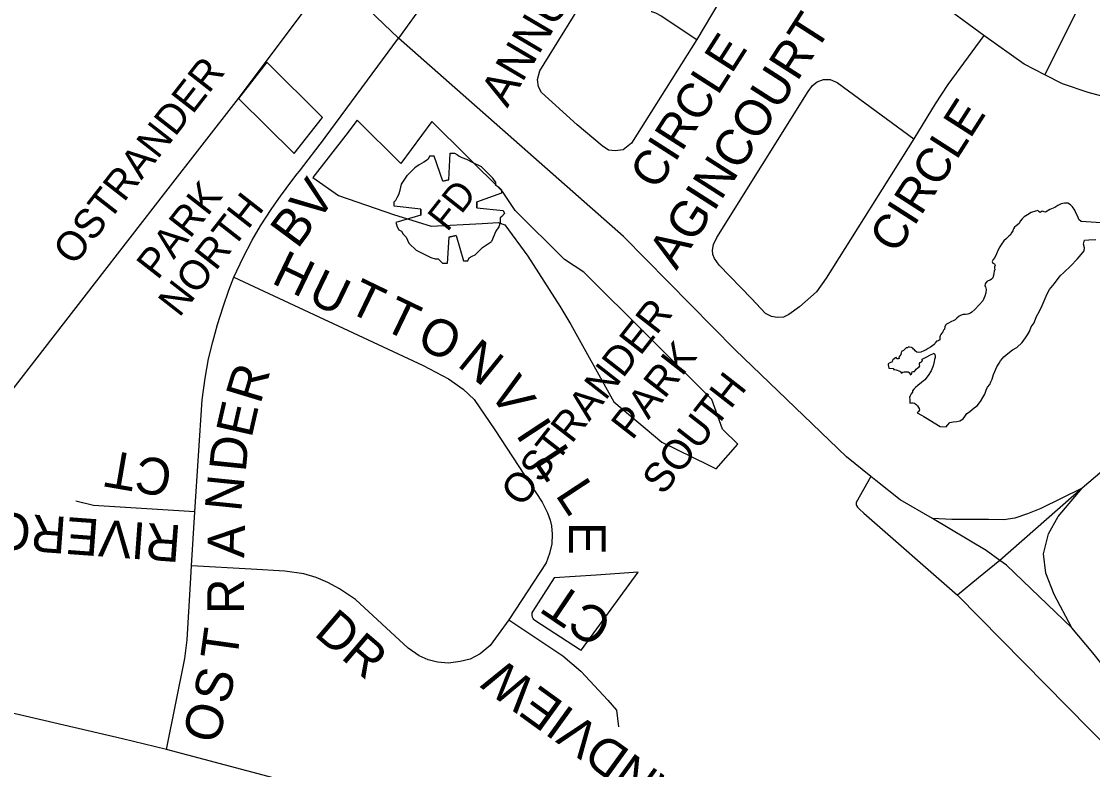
# Model space of a CAD drawing. Extents: x 586326 to 623965, y 4819854 to 4857850.
# Drawn here: x 595903 to 596631, y 4833284 to 4833792 of the extents above; entities that cross this region are included whole.
import ezdxf

# ---------------------------------------------------------------- set-up
doc = ezdxf.new("R2010")
doc.units = 0
for name, color, linetype in [('Fire Syms', 7, 'Continuous'), ('Lots_Concessions', 7, 'Continuous'), ('Major Rds and Hwys', 7, 'Continuous'), ('Minor Rd Lbls', 7, 'Continuous'), ('Minor Rds', 7, 'Continuous'), ('Park Lbls', 7, 'Continuous'), ('Park Outlines', 7, 'Continuous'), ('Proposed Secondary Rds', 7, 'Continuous'), ('SWM Ponds', 7, 'Continuous')]:
    doc.layers.add(name, color=color, linetype=linetype)

msp = doc.modelspace()

# ---------------------------------------------------------------- linework, layer by layer
at = {"layer": 'Fire Syms'}
for points in [[(596193.48, 4833684.1), (596189.48, 4833683.1), (596183.48, 4833700.1), (596180.48, 4833700.1), (596179.48, 4833698.1), (596178.48, 4833697.1), (596176.48, 4833696.1), (596173.48, 4833694.1), (596170.48, 4833692.1), (596165.48, 4833687.1), (596165.48, 4833687.1)], [(596189.48, 4833683.1), (596193.48, 4833684.1), (596194.48, 4833702.1), (596197.48, 4833702.1), (596199.48, 4833701.1), (596200.48, 4833700.1), (596202.48, 4833699.1), (596205.48, 4833698.1), (596209.48, 4833696.1), (596215.48, 4833693.1), (596215.48, 4833693.1)], [(596212.48, 4833665.1), (596212.48, 4833669.1), (596229.48, 4833675.1), (596229.48, 4833677.1), (596227.48, 4833679.1), (596225.48, 4833680.1), (596225.48, 4833682.1), (596223.48, 4833685.1), (596220.48, 4833688.1), (596215.48, 4833693.1), (596215.48, 4833693.1)], [(596174.48, 4833660.1), (596174.48, 4833664.1), (596156.48, 4833666.1), (596156.48, 4833669.1), (596157.48, 4833670.1), (596158.48, 4833672.1), (596159.48, 4833674.1), (596160.48, 4833677.1), (596161.48, 4833681.1), (596165.48, 4833687.1), (596165.48, 4833687.1)], [(596174.48, 4833664.1), (596174.48, 4833660.1), (596157.48, 4833655.1), (596158.48, 4833652.1), (596159.48, 4833650.1), (596161.48, 4833649.1), (596162.48, 4833647.1), (596164.48, 4833645.1), (596166.48, 4833641.1), (596171.48, 4833636.1), (596171.48, 4833636.1)], [(596212.48, 4833669.1), (596212.48, 4833665.1), (596230.48, 4833663.1), (596231.48, 4833661.1), (596229.48, 4833659.1), (596228.48, 4833658.1), (596228.48, 4833655.1), (596227.48, 4833652.1), (596225.48, 4833649.1), (596222.48, 4833642.1), (596222.48, 4833642.1)], [(596198.48, 4833646.1), (596193.48, 4833645.1), (596192.48, 4833627.1), (596189.48, 4833627.1), (596188.48, 4833628.1), (596186.48, 4833630.1), (596184.48, 4833630.1), (596181.48, 4833631.1), (596177.48, 4833633.1), (596171.48, 4833636.1), (596171.48, 4833636.1)], [(596193.48, 4833645.1), (596198.48, 4833646.1), (596203.48, 4833629.1), (596206.48, 4833629.1), (596207.48, 4833631.1), (596209.48, 4833632.1), (596211.48, 4833633.1), (596213.48, 4833635.1), (596216.48, 4833638.1), (596222.48, 4833642.1), (596222.48, 4833642.1)]]:
    msp.add_lwpolyline(points, dxfattribs=at)
at = {"layer": 'Lots_Concessions'}
for p, q in [((596050.57, 4833739.36), (596114.2, 4833824.24)), ((596001.39, 4833675.97), (596050.57, 4833739.36)), ((595952.86, 4833613.41), (596001.39, 4833675.97)), ((595919.29, 4833570.15), (595952.86, 4833613.41)), ((595893.72, 4833537.19), (595919.29, 4833570.15))]:
    msp.add_line(p, q, dxfattribs=at)
at = {"layer": 'Major Rds and Hwys'}
for points in [[(596159.27, 4833780.16), (596119.07, 4833818.86), (596049.17, 4833888.45), (595811.11, 4834124.39)], [(596480.17, 4833482.64), (596463.84, 4833495.81), (596388.01, 4833568.46), (596312.19, 4833645.58), (596159.27, 4833780.16)], [(596783.26, 4833664.39), (596738.71, 4833600.37), (596702.29, 4833551.85), (596673.29, 4833517.9), (596644.91, 4833492.39), (596623.81, 4833474.72)], [(596522.08, 4833454.03), (596500.2, 4833466.72), (596483.64, 4833479.84), (596480.17, 4833482.64)], [(596623.81, 4833474.72), (596595.82, 4833460.85), (596586.66, 4833457.08), (596578.01, 4833454.28), (596570.56, 4833453.15), (596560.23, 4833453.28), (596548.52, 4833453.23), (596535.26, 4833453.42), (596522.08, 4833454.03)], [(596623.81, 4833474.72), (596567.95, 4833425.57)], [(596616.94, 4833379.67), (596604.94, 4833402.45), (596599.27, 4833416.81), (596597.65, 4833429.99), (596601.01, 4833443.51), (596607.63, 4833455.47), (596623.81, 4833474.72)], [(596567.95, 4833425.57), (596558.63, 4833432.17), (596522.08, 4833454.03)], [(596567.95, 4833425.57), (596553.53, 4833413.72), (596539.11, 4833401.87)], [(596616.94, 4833379.67), (596572.38, 4833422.43), (596567.95, 4833425.57)], [(596862.2, 4833079.82), (596745.18, 4833197.47), (596737.93, 4833205.63), (596725.89, 4833220.01), (596711.58, 4833237.24), (596698.97, 4833252.43), (596673.7, 4833301.05), (596646.13, 4833343.95), (596631.01, 4833362.72), (596616.94, 4833379.67)]]:
    msp.add_lwpolyline(points, dxfattribs=at)
at = {"layer": 'Minor Rds'}
for points in [[(596598.5, 4833755.32), (596627.08, 4833812.46), (596634.65, 4833824.71), (596661.22, 4833860.39), (596671.81, 4833874.5), (596674.52, 4833879.92), (596674.98, 4833883.5), (596674.28, 4833887.55), (596673.09, 4833891.08), (596671.05, 4833893.75), (596666.24, 4833896.85), (596599.76, 4833930.5)], [(596260.05, 4833924.04), (596214.32, 4833856.49), (596159.27, 4833780.16)], [(596399.72, 4833861.41), (596382.74, 4833814.21), (596362.03, 4833779.28)], [(596280.64, 4833721.48), (596256.52, 4833743.39), (596254.47, 4833747.11), (596253.72, 4833752.18), (596255.39, 4833757.94), (596285.27, 4833806.44), (596290.51, 4833809.81), (596295.16, 4833810.89), (596298.74, 4833809.69), (596334.07, 4833797.33), (596337.91, 4833795.41), (596362.03, 4833779.28)], [(596047.52, 4833617.98), (596053.83, 4833631.22), (596059.9, 4833643), (596065.6, 4833652.87), (596072.79, 4833663.95), (596079.65, 4833673.56), (596079.77, 4833673.73), (596086.25, 4833682.37), (596090.54, 4833688.09), (596092, 4833689.99), (596109.02, 4833712.2), (596109.51, 4833712.86), (596159.27, 4833780.16)], [(596362.03, 4833779.28), (596317.56, 4833708.84), (596312.1, 4833704.44), (596306.57, 4833703.62), (596302.07, 4833704.27), (596297.63, 4833707.03), (596280.64, 4833721.48)], [(596557.12, 4833782.14), (596532.53, 4833748.78), (596523.99, 4833735.68), (596509.38, 4833711.93)], [(596399.15, 4833603.44), (596377.26, 4833626.01), (596374.09, 4833630.58), (596372.84, 4833633.3), (596372.61, 4833636.26), (596373.33, 4833640.13), (596375.67, 4833644.8), (596437.65, 4833744.1), (596440.56, 4833748.19), (596443.92, 4833750.5), (596448.09, 4833752.05), (596452.61, 4833752.05), (596457.41, 4833750.1), (596509.38, 4833711.93)], [(596509.38, 4833711.93), (596449.99, 4833617.19), (596443.3, 4833607.89), (596431.83, 4833597.67), (596424.64, 4833592.48), (596420.93, 4833590.85), (596416.72, 4833590.53), (596412.85, 4833591.23), (596408.69, 4833593.19), (596399.15, 4833603.44)], [(596020.91, 4833458.51), (596026.02, 4833534.54), (596028.02, 4833549.32), (596030.33, 4833562.38), (596033.22, 4833574.07), (596036.43, 4833585.7), (596040.32, 4833597.72), (596043.98, 4833608.99), (596047.52, 4833617.98)], [(596047.52, 4833617.98), (596176.03, 4833558.01), (596193.35, 4833548.92), (596203.36, 4833541.92), (596210.76, 4833534.84), (596224.78, 4833514.23), (596257.02, 4833465.17), (596260.53, 4833457.94), (596262.31, 4833452.88), (596263.23, 4833449.01), (596263.69, 4833443.28), (596263.46, 4833436.91), (596261.96, 4833430.28), (596259.78, 4833423.82), (596234.31, 4833385.12)], [(596480.17, 4833482.64), (596470.39, 4833464.94), (596470.27, 4833464.16), (596470.38, 4833463.47), (596470.54, 4833462.85), (596471.3, 4833461.77), (596471.85, 4833461.06), (596472.62, 4833460.27), (596475.53, 4833457.71), (596539.11, 4833401.87)], [(596020.91, 4833458.51), (595952.07, 4833462.94), (595940.23, 4833465.73)], [(596018.62, 4833421.91), (596020.91, 4833458.51)], [(596001.75, 4833297.12), (596014.28, 4833359.03), (596015.83, 4833371.58), (596017.95, 4833409.91), (596018.62, 4833421.91)], [(596234.31, 4833385.12), (596221.71, 4833367.7), (596214.89, 4833362.06), (596207.99, 4833358.59), (596201.29, 4833356.84), (596193.38, 4833355.87), (596185.78, 4833356.48), (596179.5, 4833358.08), (596173.3, 4833360.72), (596165.97, 4833365.9), (596130.07, 4833398.91), (596119.36, 4833406.35), (596111.43, 4833410.53), (596103.48, 4833413.99), (596103.35, 4833414.02), (596095.05, 4833416.35), (596082.24, 4833418.28), (596059.27, 4833419.59), (596018.62, 4833421.91)], [(596539.11, 4833401.87), (596658.77, 4833280.67), (596663.98, 4833262.94), (596660.85, 4833249.91), (596651.47, 4833240.01), (596645.47, 4833235.78), (596638.62, 4833233.51), (596632.7, 4833232.19), (596622.28, 4833231.14), (596599.87, 4833231.83), (596541.59, 4833233.58), (596530.45, 4833231.5), (596519.63, 4833226.72), (596505.16, 4833219.67), (596447.29, 4833188.89), (596420.58, 4833179.98), (596395.73, 4833177.39), (596375.33, 4833178.13), (596319.31, 4833190.37), (596283.33, 4833199.27), (596240.3, 4833216.71), (596196.15, 4833236.74), (596096.37, 4833271.98), (596001.75, 4833297.12)], [(596234.31, 4833385.12), (596271.06, 4833360.67), (596283.17, 4833350.3), (596301.57, 4833330.53), (596307.5, 4833323.95), (596308.86, 4833312.44)], [(596001.75, 4833297.12), (595971.91, 4833304.38), (595782.11, 4833348.58), (595766, 4833355.22)]]:
    msp.add_lwpolyline(points, dxfattribs=at)
at = {"layer": 'Park Outlines'}
for points in [[(596069.84, 4833763.94), (596050.57, 4833739.36), (596088.37, 4833701.86), (596107.63, 4833726.43)], [(596182.07, 4833723.68), (596161.02, 4833695.08), (596131.26, 4833724.62), (596123.64, 4833714.27), (596101.11, 4833685.51), (596118.69, 4833673.32), (596155.97, 4833660.39), (596181.55, 4833652.46), (596216.28, 4833654.34), (596227.12, 4833654.93), (596231.67, 4833653.4), (596247.33, 4833632.15), (596269.05, 4833598.23), (596276.38, 4833585.78), (596305.77, 4833533.29), (596338.27, 4833505.94), (596369.68, 4833490.44), (596375.13, 4833487.75), (596389.93, 4833504.45), (596379.6, 4833514.71), (596372.14, 4833534.94), (596285.18, 4833621.32), (596272.22, 4833629.89), (596238.67, 4833663.19), (596230.01, 4833676.09)], [(596322.19, 4833417.63), (596293.62, 4833415.63), (596265.06, 4833413.63), (596250.61, 4833391.18), (596250.04, 4833389.87), (596249.89, 4833388.45), (596250.2, 4833387.05), (596250.56, 4833386.44), (596250.92, 4833385.82), (596251.98, 4833384.87), (596283.08, 4833364.84), (596283.42, 4833364.51), (596283.63, 4833364.72)]]:
    msp.add_lwpolyline(points, close=True, dxfattribs=at)
at = {"layer": 'Proposed Secondary Rds'}
for points in [[(596557.12, 4833782.14), (596501.8, 4833822.84), (596491.55, 4833826.83), (596399.72, 4833861.41)], [(596598.5, 4833755.32), (596584.53, 4833762.57), (596557.12, 4833782.14)], [(596696.45, 4833723.56), (596671.19, 4833731.77), (596627.89, 4833743.35), (596610.55, 4833749.31), (596598.5, 4833755.32)]]:
    msp.add_lwpolyline(points, dxfattribs=at)
at = {"layer": 'SWM Ponds'}
msp.add_lwpolyline([(596636.73, 4833654.78), (596623.07, 4833655.81), (596621.52, 4833657.02), (596620.8, 4833659.08), (596619.8, 4833661.2), (596618.87, 4833663.42), (596617.39, 4833665.57), (596615.9, 4833667.07), (596614.09, 4833668.15), (596611.94, 4833668.17), (596609.67, 4833667.61), (596607.27, 4833666.66), (596605.38, 4833665.31), (596601.82, 4833663.94), (596598.86, 4833662.17), (596598.1, 4833662.27), (596596.63, 4833662.83), (596595.43, 4833661.94), (596594.69, 4833662.27), (596593.79, 4833663.14), (596592.15, 4833662.84), (596589.32, 4833661.89), (596586.72, 4833660.26), (596584.4, 4833659), (596583.04, 4833657.57), (596581.83, 4833656.02), (596581.05, 4833654.38), (596578.97, 4833652.68), (596577.99, 4833651.95), (596577.24, 4833650.79), (596576.64, 4833649.27), (596575.82, 4833647.91), (596574.94, 4833646.35), (596574, 4833645.68), (596572.42, 4833644.08), (596570.7, 4833642.52), (596569.09, 4833640.36), (596568.02, 4833638.45), (596566.71, 4833636.57), (596565.6, 4833633.86), (596564.55, 4833631.35), (596563.28, 4833629.94), (596562.6, 4833628.64), (596563.06, 4833627.53), (596564.28, 4833627.07), (596564.7, 4833626), (596564.19, 4833624.82), (596564.24, 4833624.03), (596564.55, 4833623.04), (596564.02, 4833622.04), (596563.83, 4833620.53), (596563.64, 4833619.01), (596563.18, 4833617.46), (596562.23, 4833616.46), (596561.32, 4833615.83), (596560.08, 4833615.31), (596559.05, 4833614.95), (596557.97, 4833613.46), (596557.68, 4833612.03), (596558.15, 4833611.24), (596558.6, 4833609.48), (596558.47, 4833607.17), (596557.69, 4833605.12), (596556.27, 4833601.91), (596553.77, 4833599.03), (596550.87, 4833596.06), (596548.92, 4833594.1), (596547.96, 4833593.51), (596546.28, 4833592.75), (596544.58, 4833592.49), (596542.9, 4833592.56), (596541.56, 4833592.03), (596540.18, 4833591.53), (596538.61, 4833590.17), (596537.5, 4833588.96), (596536.58, 4833588.52), (596534.54, 4833587.62), (596532.96, 4833586.77), (596531.66, 4833585.96), (596530.9, 4833585.3), (596530.58, 4833584.14), (596530.35, 4833582.58), (596529.74, 4833581.89), (596529.18, 4833581.08), (596529.16, 4833580.52), (596528.55, 4833579.79), (596527.87, 4833579.03), (596527.43, 4833578.09), (596527.14, 4833577.4), (596527.04, 4833576.31), (596527.1, 4833575.43), (596526.48, 4833574.96), (596525.91, 4833574.66), (596525.45, 4833574.39), (596524.92, 4833574.35), (596524.46, 4833573.75), (596524.03, 4833573.21), (596523.65, 4833572.72), (596523.35, 4833572.12), (596522.35, 4833571.49), (596520.76, 4833570.41), (596519.21, 4833569.37), (596517.85, 4833568.6), (596516.23, 4833567.8), (596514.23, 4833566.94), (596512.95, 4833566.69), (596511.46, 4833567.07), (596510.44, 4833567.78), (596510.02, 4833568.53), (596509.36, 4833568.96), (596508.71, 4833569.72), (596507.85, 4833570.22), (596506.47, 4833570.47), (596505.8, 4833570.58), (596505.12, 4833570.03), (596504.31, 4833569.83), (596503.43, 4833569.02), (596502.54, 4833568.22), (596501.2, 4833567.35), (596500.83, 4833566.56), (596500.76, 4833565.29), (596499.93, 4833564.44), (596499.34, 4833563.48), (596499.42, 4833562.72), (596498.81, 4833562.37), (596498.18, 4833562.52), (596497.82, 4833562.85), (596497.76, 4833563.26), (596497, 4833563.03), (596496.03, 4833562.54), (596495.11, 4833561.68), (596494.87, 4833560.95), (596495.03, 4833560.32), (596493.65, 4833559.91), (596492.03, 4833559.01), (596492.16, 4833558.33), (596492.33, 4833557.28), (596492.48, 4833556.08), (596495.68, 4833555.91), (596495.61, 4833555.3), (596496.38, 4833555.11), (596497.44, 4833554.87), (596499.9, 4833554.03), (596500.7, 4833553.57), (596500.99, 4833552.76), (596501.99, 4833553.3), (596502.93, 4833553.65), (596504.32, 4833553.73), (596505.6, 4833553.56), (596506.3, 4833553.18), (596506.67, 4833552.48), (596507.05, 4833551.68), (596507.91, 4833551.93), (596508.1, 4833552.61), (596508.35, 4833553.66), (596509.11, 4833553.9), (596509.96, 4833553.82), (596510.65, 4833554.69), (596511.07, 4833555.45), (596512.16, 4833556.26), (596513.08, 4833557.12), (596513.52, 4833557.68), (596513.42, 4833558.51), (596513.35, 4833559.27), (596513.89, 4833559.85), (596514.51, 4833560.12), (596514.8, 4833560.7), (596515.29, 4833560.96), (596515.19, 4833561.58), (596515.15, 4833562.27), (596517.8, 4833563.69), (596520.75, 4833565.18), (596522.96, 4833566.15), (596523.24, 4833566.21), (596523.42, 4833565.88), (596523.71, 4833565.24), (596523.92, 4833564.66), (596524, 4833563.97), (596523.9, 4833563.25), (596523.57, 4833561.98), (596523.21, 4833560.55), (596522.63, 4833557.68), (596521.35, 4833554.35), (596519.32, 4833551.11), (596516.96, 4833548.3), (596514.59, 4833546.33), (596512.14, 4833544.26), (596510.7, 4833543.05), (596509.4, 4833541.82), (596508.6, 4833540.79), (596508.53, 4833539.85), (596507.6, 4833538.66), (596507.06, 4833537.33), (596506.63, 4833536.25), (596506.68, 4833534.72), (596506.8, 4833533.38), (596506.87, 4833532.41), (596507.82, 4833532.66), (596508.71, 4833532.63), (596510.04, 4833532.42), (596511.09, 4833531.53), (596511.87, 4833530.5), (596512.65, 4833529.48), (596513.16, 4833528.75), (596513.27, 4833527.83), (596512.71, 4833526.68), (596511.67, 4833525.67), (596514.6, 4833524.21), (596516.2, 4833523.38), (596518.48, 4833521.84), (596523.23, 4833518.97), (596527.45, 4833516.5), (596531.48, 4833516.34), (596532.37, 4833517.47), (596533.85, 4833519.15), (596536.21, 4833519.63), (596538.79, 4833519.94), (596540.79, 4833520.38), (596543.07, 4833521.59), (596544.18, 4833523.22), (596545.5, 4833525.34), (596547.41, 4833526.51), (596550.69, 4833529.43), (596552.52, 4833530.5), (596554.68, 4833533.47), (596556.41, 4833536.11), (596557.82, 4833538.34), (596558.58, 4833541.23), (596559.54, 4833543.31), (596561.09, 4833545.09), (596561.71, 4833546.94), (596562.61, 4833548.73), (596563.64, 4833551.75), (596564.6, 4833553.83), (596565.97, 4833557.08), (596567.36, 4833559.49), (596568.46, 4833561.12), (596570.74, 4833563.82), (596573.36, 4833566.1), (596576.42, 4833568.53), (596579.49, 4833570.13), (596583.07, 4833573.65), (596585.31, 4833576.72), (596586.66, 4833578.66), (596587.99, 4833581.11), (596589.31, 4833584.07), (596591.2, 4833586.92), (596592.61, 4833590.64), (596595.03, 4833595.23), (596596.71, 4833598.66), (596598.09, 4833601.91), (596600.13, 4833606.55), (596601.62, 4833609.62), (596605.14, 4833613.7), (596608.8, 4833618.82), (596611.42, 4833621.1), (596616.2, 4833625.51), (596620.4, 4833630.04), (596623.17, 4833633.37), (596625.31, 4833635.69), (596625.33, 4833637.83), (596624.83, 4833640.39), (596625.43, 4833643.08), (596628.29, 4833643.33), (596633.04, 4833643.45)], dxfattribs=at)

# ---------------------------------------------------------------- texts
at = {"layer": 'Fire Syms'}
msp.add_text('FD', height=18.738, rotation=51.66545, dxfattribs=at).set_placement((596192.48, 4833648.1))
at = {"layer": 'Minor Rd Lbls'}
for s, height, rotation, p in [('ANNUAL', 22.544, 59.43462, (596233.26, 4833732.35)), ('AGINCOURT', 24.383, 57.38688, (596348.19, 4833622.07)), ('CIRCLE', 23.445, 57.38688, (596334.98, 4833676.22)), ('CIRCLE', 23.211, 57.38688, (596497.58, 4833632.96)), ('BV', 25.002, 53.44038, (596090.72, 4833636.49)), ('H', 25, 334.2419, (596072.22, 4833614.26)), ('U', 25, 334.2419, (596096.54, 4833601.74)), ('T', 25, 334.2419, (596123.48, 4833595.1)), ('T', 25, 334.2419, (596147.48, 4833583.1)), ('O', 25, 334.2419, (596170.48, 4833571.1)), ('N', 25, 321.00903, (596198.48, 4833558.1)), ('R', 25, 73.17861, (596065.48, 4833531.1)), ('V', 25, 303.36638, (596220.48, 4833540.1)), ('E', 25, 77.12502, (596059.48, 4833508.1)), ('I', 25, 303.36638, (596238.48, 4833511.1)), ('D', 25, 84.19329, (596055.48, 4833485.1)), ('L', 25, 303.36638, (596250.48, 4833493.1)), ('CT', 25.002, 170.20524, (596006.96, 4833492.93)), ('N', 25, 84.19329, (596052.48, 4833458.1)), ('L', 25, 303.36638, (596265.48, 4833470.1)), ('RIVERCREST', 25.002, 175.80214, (596012.35, 4833449.26)), ('A', 25, 88.56792, (596054.48, 4833427.1)), ('E', 25, 270.00002, (596275.17, 4833451.72)), ('R', 25, 90.00002, (596054.48, 4833389.1)), ('CT', 25.002, 146.15569, (596306.47, 4833386.21)), ('DR', 25.002, 319.39133, (596101.2, 4833375.12)), ('T', 25, 82.03041, (596049.48, 4833357.1)), ('S', 25, 75.32363, (596043.48, 4833327.1)), ('GRANDVIEW', 25.002, 144.08238, (596395.99, 4833238.97)), ('O', 25, 75.32363, (596036.48, 4833300.1))]:
    msp.add_text(s, height=height, rotation=rotation, dxfattribs=at).set_placement(p)
at = {"layer": 'Park Lbls'}
for s, p in [('OSTRANDER', (595938.93, 4833624.98)), ('PARK', (595995.67, 4833615.43)), ('NORTH', (596010.41, 4833590.02)), ('OSTRANDER', (596243.18, 4833460.98)), ('PARK', (596318.14, 4833506.64)), ('SOUTH', (596339.18, 4833469.17))]:
    msp.add_text(s, height=19.992, rotation=52.00002, dxfattribs=at).set_placement(p)

doc.saveas('drawing.dxf')
